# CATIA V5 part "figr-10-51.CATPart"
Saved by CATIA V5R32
Part number: Part1
Bounding box of the stored display mesh (mm): x -68.386 to 32.095, y 0 to 344, z -0.079 to 67.481
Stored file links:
  D:\PROJECTS\Project 2022\CATIA V5 6R 2022\Resources\Part Files\c10_catia_v5_6r2022_prt\c10_catia_v5_6r2022_prt\figr-10-51.CATPart
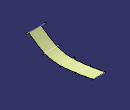
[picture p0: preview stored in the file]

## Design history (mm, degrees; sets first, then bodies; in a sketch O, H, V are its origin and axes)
Body1 (main body)
  Plane1: type Offset, RefPlane zx-plane, Offset 86
  Plane2: type Offset, RefPlane Plane1, Offset 86
  Plane3: type Offset, RefPlane Plane2, Offset 86
  Plane4: type Offset, RefPlane Plane3, Offset 86
  Sketch1 on zx-plane, origin (0, 0, 0), H (-1, 0, 0), V (0, 0, 1)
    line L1 (-32.0954, 67.4806) -> (68.3859, 67.4806)
    horizontal: L1 H
  Sketch2 on Plane1, origin (0, 86, 0), H (-1, 0, 0), V (0, 0, 1)
    line L1 (-24.4409, 14.2252) -> (55.9283, 14.2252)
    horizontal: L1 H
  Sketch3 on Plane2, origin (0, 172, 0), H (-1, 0, 0), V (0, 0, 1)
    line L1 (-24.2042, 0) -> (53.3039, 0)
    point P1 (-24.2042, 0)
    coincidence: P1 H
    horizontal: L1 H
  Sketch4 on Plane3, origin (0, 258, 0), H (-1, 0, 0), V (0, 0, 1)
    line L1 (-23.6533, 8.5985) -> (50.1324, 8.5985)
    horizontal: L1 H
  Sketch5 on Plane4, origin (0, 344, 0), H (-1, 0, 0), V (0, 0, 1)
    line L1 (-20.9465, 23.2339) -> (46.0713, 23.2339)
    horizontal: L1 H
  Sweep1: type Conic, Guide (Sketch1; Sketch2; Sketch3; Sketch4; Sketch5)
